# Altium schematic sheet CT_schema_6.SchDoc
size 364 x 340 mm
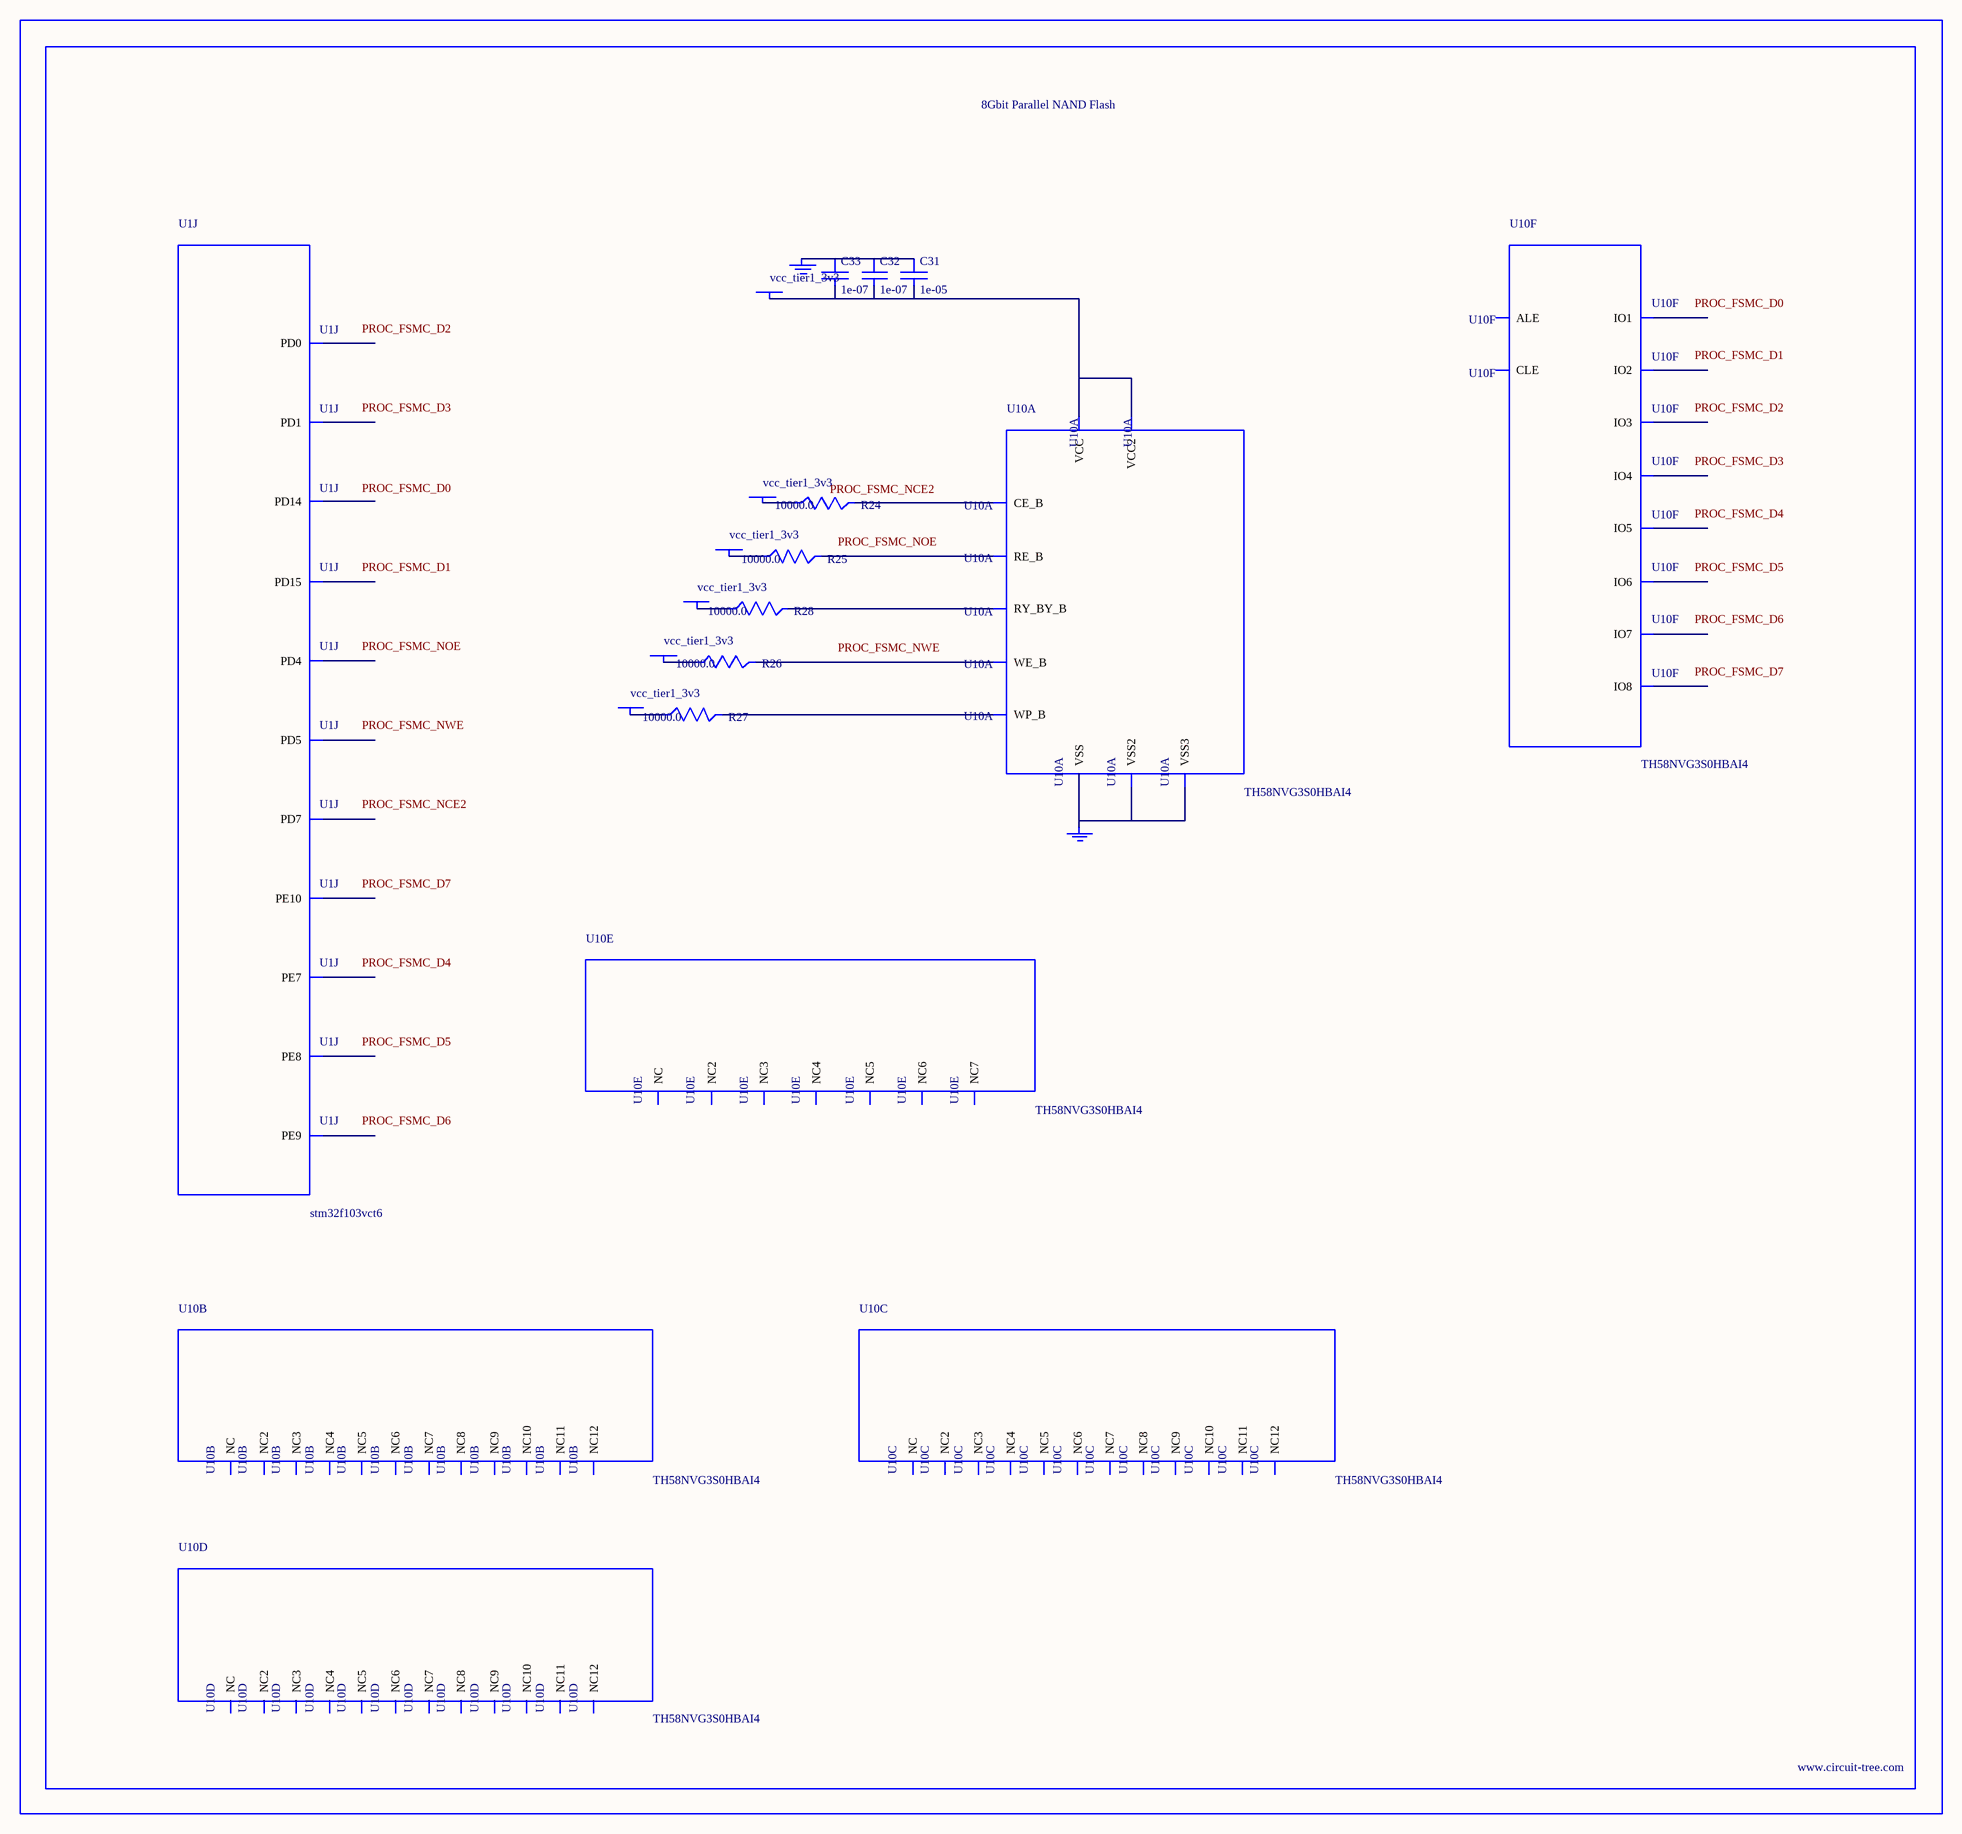
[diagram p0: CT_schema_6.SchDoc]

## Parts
BORDER5  (no value)
C31  1e-05  [C0805]
C32  1e-07  [C0402]
C33  1e-07  [C0402]
GND_INSTANCE_5_0  (no value)
GND_INSTANCE_5_1  (no value)
POWER_INSTANCE_5_0  vcc_tier1_3v3
POWER_INSTANCE_5_1  vcc_tier1_3v3
POWER_INSTANCE_5_2  vcc_tier1_3v3
POWER_INSTANCE_5_3  vcc_tier1_3v3
POWER_INSTANCE_5_4  vcc_tier1_3v3
POWER_INSTANCE_5_5  vcc_tier1_3v3
R24  10000.0  [R0603]
R25  10000.0  [R0603]
R26  10000.0  [R0603]
R27  10000.0  [R0603]
R28  10000.0  [R0603]
U1  stm32f103vct6  [LQFP100]  (part J of 10)
U10  TH58NVG3S0HBAI4  [TH58NVG3S0HBAI4]  (parts A,B,C,D,E,F of 6)

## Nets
NetC31_1: C31.1 C32.1 C33.1 GND_INSTANCE_5_0.0(GND)
NetC31_2: C31.2 C32.2 C33.2 POWER_INSTANCE_5_5.0(PWR) U10.H8(VCC) U10.J6(VCC2)
NetGND_INSTANCE_5_1_0: GND_INSTANCE_5_1.0(GND) U10.C5(VSS) U10.K3(VSS2) U10.K8(VSS3)
NetPOWER_INSTANCE_5_0_0: POWER_INSTANCE_5_0.0(PWR) R24.1
NetPOWER_INSTANCE_5_1_0: POWER_INSTANCE_5_1.0(PWR) R25.1
NetPOWER_INSTANCE_5_2_0: POWER_INSTANCE_5_2.0(PWR) R26.1
NetPOWER_INSTANCE_5_3_0: POWER_INSTANCE_5_3.0(PWR) R27.1
NetPOWER_INSTANCE_5_4_0: POWER_INSTANCE_5_4.0(PWR) R28.1
NetR24_2: R24.2 U10.C6(CE_B)
NetR25_2: R25.2 U10.D4(RE_B)
NetR26_2: R26.2 U10.C7(WE_B)
NetR27_2: R27.2 U10.C3(WP_B)
NetR28_2: R28.2 U10.C8(RY_BY_B)

Not connected (* = marked no-connect by the designer): U1 38(PE7) 39(PE8) 40(PE9) 41(PE10) 61(PD14) 62(PD15) 81(PD0) 82(PD1) 85(PD4) 86(PD5) 88(PD7); U10 A1(NC) A2(NC3) A9(NC4) A10(NC2) B1(NC5) B9(NC7) B10(NC6) C4(ALE) D3(NC8) D5(CLE) D6(NC9) D7(NC10) D8(NC11) E3(NC12) E4(NC) E5(NC2) E6(NC3) E7(NC4) E8(NC5) F3(NC6) F4(NC7) F5(NC8) F6(NC9) F7(NC10) F8(NC11) G3(NC12) G4(NC) G5(NC2) G6(NC3) G7(NC4) G8(NC5) H3(NC6) H4(IO1) H5(NC7) H6(NC8) H7(NC9) J3(NC10) J4(IO2) J5(NC11) J7(IO6) J8(IO8) K4(IO3) K5(IO4) K6(IO5) K7(IO7) L1(NC12) L2(NC2) L9(NC3) L10(NC) M1(NC4) M2(NC6) M9(NC7) M10(NC5)

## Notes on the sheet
- Labels drawn without touching a wire or pin: PROC_FSMC_D0, PROC_FSMC_D1, PROC_FSMC_D2, PROC_FSMC_D3, PROC_FSMC_D4, PROC_FSMC_D5, PROC_FSMC_D6, PROC_FSMC_D7, PROC_FSMC_NCE2, PROC_FSMC_NOE, PROC_FSMC_NWE

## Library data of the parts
BORDER5 = BORDER_PAGE5
C31 = C0805C106K8RACTU
C32 C33 = C0402C104K3RACTU
GND_INSTANCE_5_0 GND_INSTANCE_5_1 = GND
POWER_INSTANCE_5_0-POWER_INSTANCE_5_5 = PWR
R24-R28 = RC0603JR-0710KL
